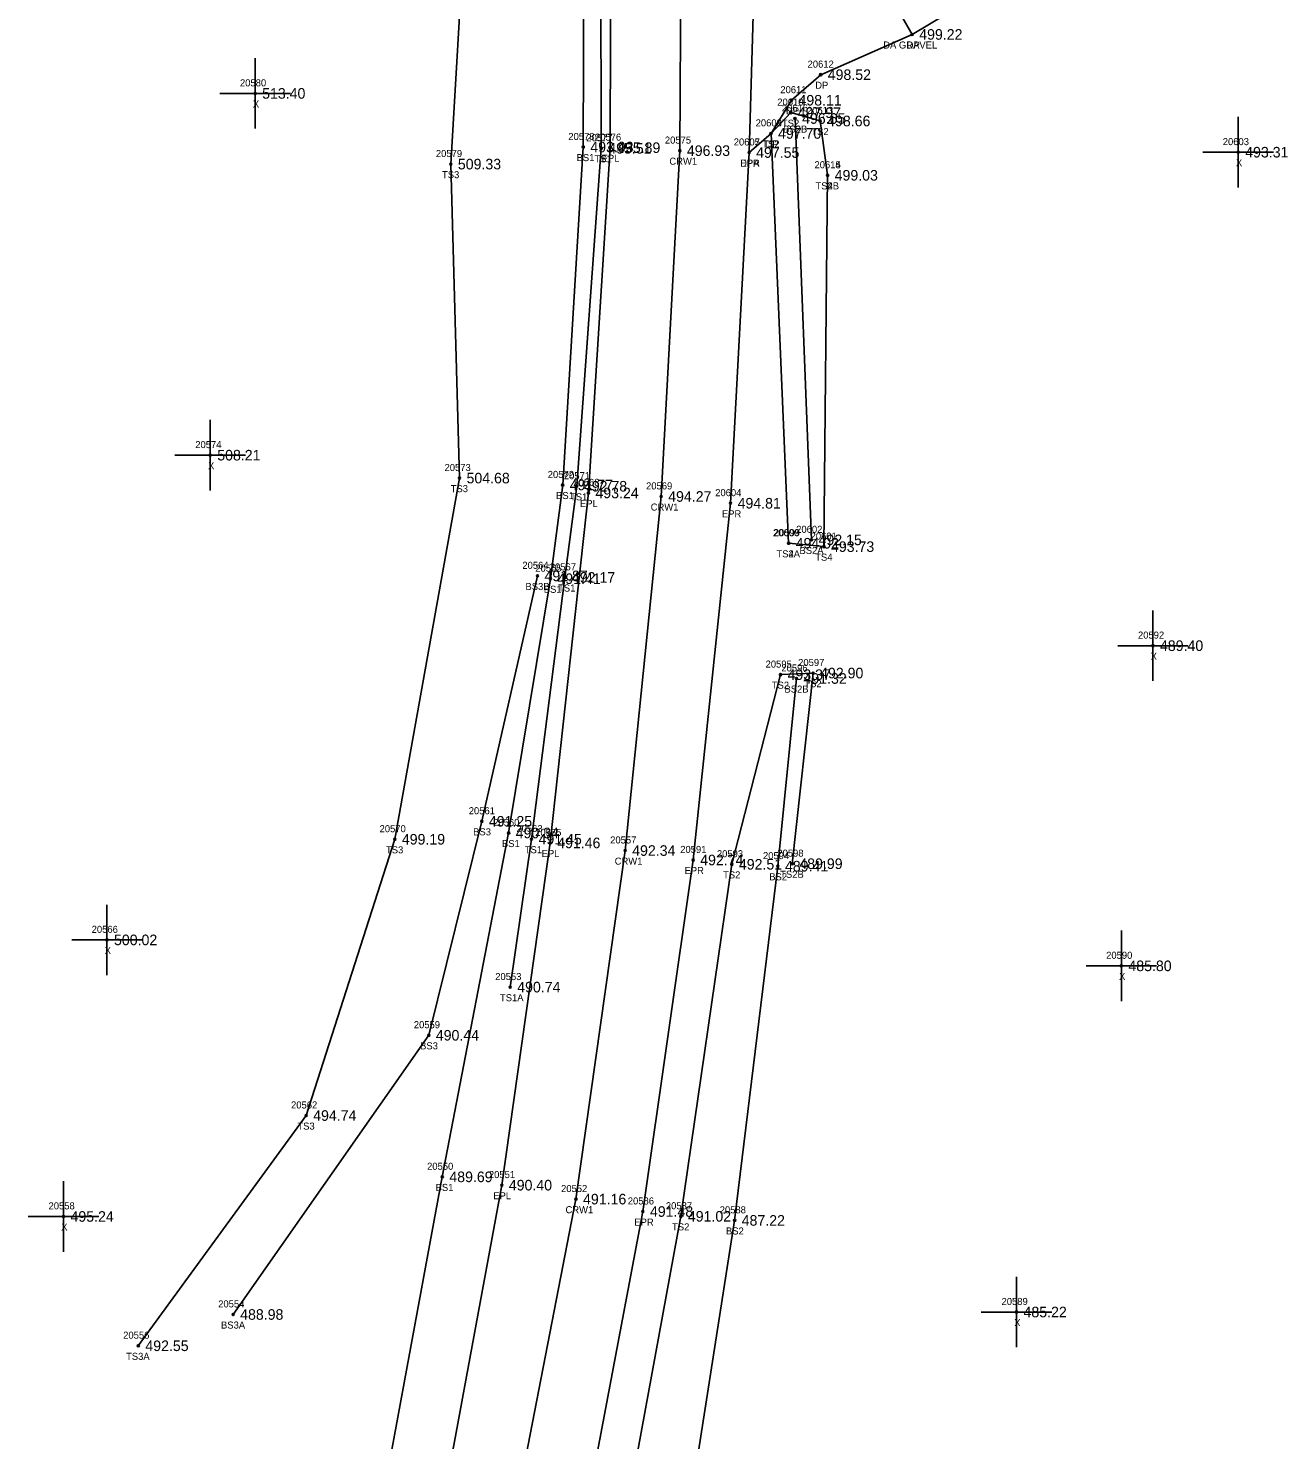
# Model space of a CAD drawing. Extents: x 1649406 to 1650436, y 896752 to 898178.
# Drawn here: x 1649852.5 to 1650031.2, y 897580 to 897780.3 of the extents above; entities that cross this region are included whole.
import ezdxf

# ---------------------------------------------------------------- set-up
doc = ezdxf.new("R2010")
doc.units = 0
for name, color, linetype in [('RD_DTM_BkLn1', 7, 'Continuous'), ('RD_DTM_BkLn2', 7, 'Continuous'), ('RD_DTM_BkLn_txCode', 7, 'Continuous'), ('RD_EX_Driveway', 7, 'Continuous'), ('RD_EX_Driveway_txCode', 7, 'Continuous'), ('RD_EX_Misc', 7, 'Continuous'), ('RD_EX_Misc_txCode', 7, 'Continuous'), ('RD_EX_Road', 7, 'Continuous'), ('RD_EX_Road_txCode', 7, 'Continuous'), ('RD_EX_TX_Driveway_ELEV', 7, 'Continuous'), ('RD_EX_TX_Misc_ELEV', 7, 'Continuous'), ('RD_EX_TX_Road_ELEV', 7, 'Continuous'), ('RD_HC_Survey_ELEV', 7, 'Continuous'), ('RD_HC_Survey_txCode', 7, 'Continuous'), ('RD_SMD_Locator', 7, 'Continuous')]:
    doc.layers.add(name, color=color, linetype=linetype)

msp = doc.modelspace()

# ---------------------------------------------------------------- linework, layer by layer
at = {"layer": 'RD_DTM_BkLn1'}
msp.add_lwpolyline([(1649894.9, 897462.66), (1649908.82, 897514.7), (1649920.62, 897564.87), (1649930.21, 897614.13), (1649937.18, 897663.59), (1649942.29, 897713.83), (1649944.94, 897762.9), (1649945.25, 897813.29), (1649942.44, 897857.84), (1649938.23, 897907.76), (1649931.88, 897958.19), (1649923.51, 898006.94), (1649914.47, 898059.31), (1649904.54, 898110.23), (1649895.09, 898157.93)], dxfattribs=at)
at = {"layer": 'RD_DTM_BkLn2'}
msp.add_line((1649963.63, 897707.67), (1649961.29, 897767.46), dxfattribs=at)
for points in [[(1649920.87, 897644.21), (1649923.9, 897665.21), (1649928.63, 897702.34), (1649930.33, 897715.28), (1649933.79, 897763.23), (1649933.69, 897813.91), (1649929.49, 897857.74), (1649925.75, 897907.07), (1649919.24, 897954.42), (1649910.51, 898004.53), (1649900.99, 898055.57), (1649897.4, 898076.37), (1649890.54, 898075.59)], [(1649902.31, 897569.09), (1649911.24, 897617.29), (1649920.65, 897666.08), (1649926.58, 897702.16), (1649928.32, 897715.46), (1649931.24, 897763.41), (1649931.43, 897814), (1649927.03, 897856.89), (1649923.37, 897907.61), (1649916.38, 897954.04), (1649907.99, 898004.31), (1649897.74, 898054.92), (1649893.88, 898075.41)], [(1649868.11, 897593.32), (1649891.92, 897625.99), (1649904.5, 897665.19), (1649913.68, 897716.44), (1649912.45, 897760.99), (1649915.73, 897816.74), (1649911.68, 897855.77), (1649908.62, 897888.32), (1649894.21, 898001.99), (1649884.42, 898052.27), (1649879.49, 898066.69)], [(1649960.38, 897707.19), (1649957.88, 897765.34), (1649960.67, 897768.29), (1649964.85, 897767.11), (1649965.91, 897759.4)], [(1649960.38, 897707.19), (1649965.39, 897706.71), (1649965.91, 897759.4)], [(1649881.56, 897597.76), (1649909.32, 897637.38), (1649916.85, 897667.74), (1649924.74, 897702.56)], [(1649933.78, 897483.58), (1649920, 897487.26), (1649924.82, 897510.73), (1649935.93, 897561.68), (1649945.08, 897611.69), (1649952.32, 897661.64), (1649959.23, 897688.55), (1649963.85, 897688.77), (1649960.9, 897661.72)], [(1649935.25, 897487.64), (1649929.59, 897490.86), (1649933.49, 897510.48), (1649944.91, 897561.12), (1649952.72, 897611.11), (1649958.86, 897661.37), (1649961.49, 897688)]]:
    msp.add_lwpolyline(points, dxfattribs=at)
at = {"layer": 'RD_EX_Driveway'}
for points in [[(1649977.91, 897779.39), (1649995.36, 897789.82), (1650019.52, 897810.91)], [(1649954.77, 897762.63), (1649957.88, 897765.34), (1649960.78, 897770.05), (1649964.93, 897773.68), (1649977.91, 897779.39), (1649972.2, 897789.45), (1649962.67, 897788.68), (1649955.64, 897791.88)]]:
    msp.add_lwpolyline(points, dxfattribs=at)
at = {"layer": 'RD_EX_Misc'}
for p, q in [((1649884.68, 897766.02), (1649884.68, 897776.02)), ((1649879.68, 897771.02), (1649889.68, 897771.02)), ((1650024.16, 897757.68), (1650024.16, 897767.68)), ((1650019.16, 897762.68), (1650029.16, 897762.68)), ((1649878.31, 897714.69), (1649878.31, 897724.69)), ((1649873.31, 897719.69), (1649883.31, 897719.69)), ((1650012.07, 897687.66), (1650012.07, 897697.66)), ((1650007.07, 897692.66), (1650017.07, 897692.66)), ((1649863.66, 897645.91), (1649863.66, 897655.91)), ((1649858.66, 897650.91), (1649868.66, 897650.91)), ((1650007.59, 897642.23), (1650007.59, 897652.23)), ((1650002.59, 897647.23), (1650012.59, 897647.23)), ((1649857.49, 897606.67), (1649857.49, 897616.67)), ((1649852.49, 897611.67), (1649862.49, 897611.67)), ((1649992.71, 897593.11), (1649992.71, 897603.11)), ((1649987.71, 897598.11), (1649997.71, 897598.11))]:
    msp.add_line(p, q, dxfattribs=at)
at = {"layer": 'RD_EX_Road'}
for points in [[(1649905.13, 897459.2), (1649918.81, 897511.88), (1649930.39, 897563.05), (1649939.7, 897612.37), (1649946.83, 897662.25), (1649952.14, 897712.87), (1649954.77, 897762.63), (1649955.64, 897791.88), (1649955.33, 897812.31), (1649952.46, 897859.75), (1649947.95, 897909.71), (1649941.78, 897959.51), (1649933.15, 898009.23), (1649924.03, 898060.85), (1649913.91, 898112.48), (1649904.76, 898159.93)], [(1649885.84, 897465.29), (1649899.42, 897516.76), (1649910.69, 897567.43), (1649919.68, 897616.11), (1649926.54, 897664.67), (1649931.97, 897714.33), (1649935.04, 897763.32), (1649935.22, 897813.54), (1649932.16, 897857.76), (1649927.73, 897907.79), (1649922.24, 897954.81), (1649913.41, 898005.06), (1649903.99, 898056.19), (1649899.68, 898079.2), (1649896.48, 898096.53), (1649894.5, 898108.47), (1649884.77, 898155.82)]]:
    msp.add_lwpolyline(points, dxfattribs=at)
at = {"layer": 'RD_SMD_Locator'}
for centre in [(1649977.91, 897779.39), (1649977.91, 897779.39), (1649964.93, 897773.68), (1649884.68, 897771.02), (1649960.67, 897768.29), (1649960.78, 897770.05), (1649961.29, 897767.46), (1649964.85, 897767.11), (1649957.88, 897765.34), (1649957.88, 897765.34), (1649931.24, 897763.41), (1649933.79, 897763.23), (1649935.04, 897763.32), (1649944.94, 897762.9), (1649954.77, 897762.63), (1649954.77, 897762.63), (1650024.16, 897762.68), (1649912.45, 897760.99), (1649965.91, 897759.4), (1649965.91, 897759.4), (1649878.31, 897719.69), (1649913.68, 897716.44), (1649928.32, 897715.46), (1649930.33, 897715.28), (1649931.97, 897714.33), (1649942.29, 897713.83), (1649952.14, 897712.87), (1649960.38, 897707.19), (1649960.38, 897707.19), (1649963.63, 897707.67), (1649965.39, 897706.71), (1649924.74, 897702.56), (1649928.63, 897702.34), (1649926.58, 897702.16), (1650012.07, 897692.66), (1649959.23, 897688.55), (1649963.85, 897688.77), (1649961.49, 897688), (1649916.85, 897667.74), (1649904.5, 897665.19), (1649920.65, 897666.08), (1649923.9, 897665.21), (1649926.54, 897664.67), (1649937.18, 897663.59), (1649946.83, 897662.25), (1649952.32, 897661.64), (1649958.86, 897661.37), (1649960.9, 897661.72), (1649863.66, 897650.91), (1650007.59, 897647.23), (1649920.87, 897644.21), (1649909.32, 897637.38), (1649891.92, 897625.99), (1649911.24, 897617.29), (1649919.68, 897616.11), (1649930.21, 897614.13), (1649939.7, 897612.37), (1649857.49, 897611.67), (1649945.08, 897611.69), (1649952.72, 897611.11), (1649992.71, 897598.11), (1649881.56, 897597.76), (1649868.11, 897593.32)]:
    msp.add_circle(centre, 0.15, dxfattribs=at)

# ---------------------------------------------------------------- texts
at = {"layer": 'RD_DTM_BkLn_txCode'}
for s, p in [('20610', (1649958.77, 897769.29)), ('20616', (1649959.41, 897768.46)), ('20613', (1649962.99, 897768.11)), ('20609', (1649955.7, 897766.34)), ('TS2', (1649959.43, 897766.29)), ('BS2B', (1649959.59, 897765.46)), ('20578', (1649929.12, 897764.41)), ('20577', (1649931.67, 897764.23)), ('TS2', (1649963.6, 897765.11)), ('20579', (1649910.33, 897761.99)), ('BS1', (1649930.29, 897761.41)), ('TS2', (1649956.63, 897763.34)), ('TS1', (1649932.83, 897761.23)), ('20614', (1649964.05, 897760.4)), ('20615', (1649964.05, 897760.4)), ('TS3', (1649911.2, 897758.99)), ('TS2B', (1649964.19, 897757.4)), ('TS4B', (1649964.19, 897757.4)), ('20573', (1649911.56, 897717.44)), ('20572', (1649926.2, 897716.46)), ('20571', (1649928.49, 897716.28)), ('TS3', (1649912.43, 897714.44)), ('BS1', (1649927.38, 897713.46)), ('TS1', (1649929.37, 897713.28)), ('20600', (1649958.16, 897708.19)), ('20599', (1649958.27, 897708.19)), ('20602', (1649961.45, 897708.67)), ('20601', (1649963.5, 897707.71)), ('BS2A', (1649961.92, 897705.67)), ('20564', (1649922.6, 897703.56)), ('20567', (1649926.49, 897703.34)), ('TS2A', (1649958.65, 897705.19)), ('TS4A', (1649958.65, 897705.19)), ('TS4', (1649964.15, 897704.71)), ('20565', (1649924.44, 897703.16)), ('BS3B', (1649923.04, 897700.56)), ('BS1', (1649925.64, 897700.16)), ('TS1', (1649927.67, 897700.34)), ('20595', (1649957.11, 897689.55)), ('20597', (1649961.73, 897689.77)), ('20596', (1649959.35, 897689)), ('TS2', (1649957.99, 897686.55)), ('BS2B', (1649959.79, 897686)), ('TS2', (1649962.61, 897686.77)), ('20561', (1649914.99, 897668.74)), ('20570', (1649902.34, 897666.19)), ('BS3', (1649915.62, 897665.74)), ('20560', (1649918.46, 897667.08)), ('20563', (1649921.76, 897666.21)), ('BS1', (1649919.7, 897664.08)), ('TS3', (1649903.25, 897663.19)), ('TS1', (1649922.94, 897663.21)), ('20593', (1649950.2, 897662.64)), ('20594', (1649956.74, 897662.37)), ('20598', (1649958.78, 897662.72)), ('TS2', (1649951.08, 897659.64)), ('BS2', (1649957.63, 897659.37)), ('TS2B', (1649959.18, 897659.72)), ('20553', (1649918.75, 897645.21)), ('TS1A', (1649919.42, 897642.21)), ('20559', (1649907.2, 897638.38)), ('BS3', (1649908.09, 897635.38)), ('20562', (1649889.78, 897626.99)), ('TS3', (1649890.68, 897623.99)), ('20550', (1649909.08, 897618.29)), ('BS1', (1649910.29, 897615.29)), ('20587', (1649942.96, 897612.69)), ('20588', (1649950.6, 897612.11)), ('TS2', (1649943.84, 897609.69)), ('BS2', (1649951.49, 897609.11)), ('20554', (1649879.44, 897598.76)), ('BS3A', (1649879.84, 897595.76)), ('20556', (1649865.96, 897594.32)), ('TS3A', (1649866.37, 897591.32))]:
    msp.add_text(s, height=1, dxfattribs=at).set_placement(p)
at = {"layer": 'RD_EX_Driveway_txCode'}
for s, p in [('DA GRAVEL', (1649973.8, 897777.39)), ('DP', (1649977.13, 897777.39)), ('20612', (1649963.07, 897774.68)), ('DP', (1649964.15, 897771.68)), ('20611', (1649959.2, 897771.05)), ('DP', (1649960, 897768.05)), ('20608', (1649955.7, 897766.34)), ('20607', (1649952.59, 897763.63)), ('DP', (1649957.1, 897763.34)), ('DPA', (1649953.5, 897760.63))]:
    msp.add_text(s, height=1, dxfattribs=at).set_placement(p)
at = {"layer": 'RD_EX_Misc_txCode'}
for s, p in [('20580', (1649882.53, 897772.02)), ('X', (1649884.37, 897769.02)), ('20603', (1650021.98, 897763.68)), ('X', (1650023.85, 897760.68)), ('20574', (1649876.19, 897720.69)), ('X', (1649878, 897717.69)), ('20592', (1650009.95, 897693.66)), ('X', (1650011.75, 897690.66)), ('20566', (1649861.49, 897651.91)), ('X', (1649863.34, 897648.91)), ('20590', (1650005.43, 897648.23)), ('X', (1650007.27, 897645.23)), ('20558', (1649855.37, 897612.67)), ('X', (1649857.17, 897609.67)), ('20589', (1649990.59, 897599.11)), ('X', (1649992.39, 897596.11))]:
    msp.add_text(s, height=1, dxfattribs=at).set_placement(p)
at = {"layer": 'RD_EX_Road_txCode'}
for s, p in [('20576', (1649932.9, 897764.32)), ('20605', (1649952.59, 897763.63)), ('EPL', (1649933.84, 897761.32)), ('EPR', (1649953.54, 897760.63)), ('20568', (1649929.83, 897715.33)), ('20604', (1649949.96, 897713.87)), ('EPL', (1649930.77, 897712.33)), ('EPR', (1649950.91, 897710.87)), ('20555', (1649924.42, 897665.67)), ('EPL', (1649925.33, 897662.67)), ('20591', (1649945, 897663.25)), ('EPR', (1649945.61, 897660.25)), ('20551', (1649917.85, 897617.11)), ('EPL', (1649918.47, 897614.11)), ('20586', (1649937.56, 897613.37)), ('EPR', (1649938.48, 897610.37))]:
    msp.add_text(s, height=1, dxfattribs=at).set_placement(p)
at = {"layer": 'RD_EX_TX_Driveway_ELEV'}
for s, p in [('499.22', (1649978.91, 897778.64)), ('499.22', (1649978.91, 897778.64)), ('498.52', (1649965.93, 897772.93)), ('498.11', (1649961.78, 897769.3)), ('497.70', (1649958.88, 897764.59)), ('497.55', (1649955.77, 897761.88))]:
    msp.add_text(s, height=1.5, dxfattribs=at).set_placement(p)
at = {"layer": 'RD_EX_TX_Misc_ELEV'}
for s, p in [('513.40', (1649885.68, 897770.27)), ('497.97', (1649961.67, 897767.54)), ('496.65', (1649962.29, 897766.71)), ('498.66', (1649965.85, 897766.36)), ('497.70', (1649958.88, 897764.59)), ('493.93', (1649932.24, 897762.66)), ('495.51', (1649934.79, 897762.48)), ('493.31', (1650025.16, 897761.93)), ('509.33', (1649913.45, 897760.24)), ('499.03', (1649966.91, 897758.65)), ('499.03', (1649966.91, 897758.65)), ('508.21', (1649879.31, 897718.94)), ('504.68', (1649914.68, 897715.69)), ('491.77', (1649929.32, 897714.71)), ('492.78', (1649931.33, 897714.53)), ('492.15', (1649964.63, 897706.92)), ('494.02', (1649961.38, 897706.44)), ('494.02', (1649961.38, 897706.44)), ('493.73', (1649966.39, 897705.96)), ('491.87', (1649925.74, 897701.81)), ('491.41', (1649927.58, 897701.41)), ('492.17', (1649929.63, 897701.59)), ('489.40', (1650013.07, 897691.91)), ('493.37', (1649960.23, 897687.8)), ('491.32', (1649962.49, 897687.25)), ('492.90', (1649964.85, 897688.02)), ('491.25', (1649917.85, 897666.99)), ('490.34', (1649921.65, 897665.33)), ('499.19', (1649905.5, 897664.44)), ('491.45', (1649924.9, 897664.46)), ('492.51', (1649953.32, 897660.89)), ('489.99', (1649961.9, 897660.97)), ('489.41', (1649959.86, 897660.62)), ('500.02', (1649864.66, 897650.16)), ('485.80', (1650008.59, 897646.48)), ('490.74', (1649921.87, 897643.46)), ('490.44', (1649910.32, 897636.63)), ('494.74', (1649892.92, 897625.24)), ('489.69', (1649912.24, 897616.54)), ('495.24', (1649858.49, 897610.92)), ('491.02', (1649946.08, 897610.94)), ('487.22', (1649953.72, 897610.36)), ('488.98', (1649882.56, 897597.01)), ('485.22', (1649993.71, 897597.36)), ('492.55', (1649869.11, 897592.57))]:
    msp.add_text(s, height=1.5, dxfattribs=at).set_placement(p)
at = {"layer": 'RD_EX_TX_Road_ELEV'}
for s, p in [('495.89', (1649936.04, 897762.57)), ('497.55', (1649955.77, 897761.88)), ('493.24', (1649932.97, 897713.58)), ('494.81', (1649953.14, 897712.12)), ('491.46', (1649927.54, 897663.92)), ('492.74', (1649947.83, 897661.5)), ('490.40', (1649920.68, 897615.36)), ('491.48', (1649940.7, 897611.62))]:
    msp.add_text(s, height=1.5, dxfattribs=at).set_placement(p)
at = {"layer": 'RD_HC_Survey_ELEV'}
for s, p in [('496.93', (1649945.94, 897762.15)), ('494.27', (1649943.29, 897713.08)), ('492.34', (1649938.18, 897662.84)), ('491.16', (1649931.21, 897613.38))]:
    msp.add_text(s, height=1.5, dxfattribs=at).set_placement(p)
at = {"layer": 'RD_HC_Survey_txCode'}
for s, p in [('20575', (1649942.82, 897763.9)), ('CRW1', (1649943.46, 897760.9)), ('20569', (1649940.15, 897714.83)), ('CRW1', (1649940.81, 897711.83)), ('20557', (1649935.06, 897664.59)), ('CRW1', (1649935.7, 897661.59)), ('20552', (1649928.09, 897615.13)), ('CRW1', (1649928.72, 897612.13))]:
    msp.add_text(s, height=1, dxfattribs=at).set_placement(p)

doc.saveas('drawing.dxf')
